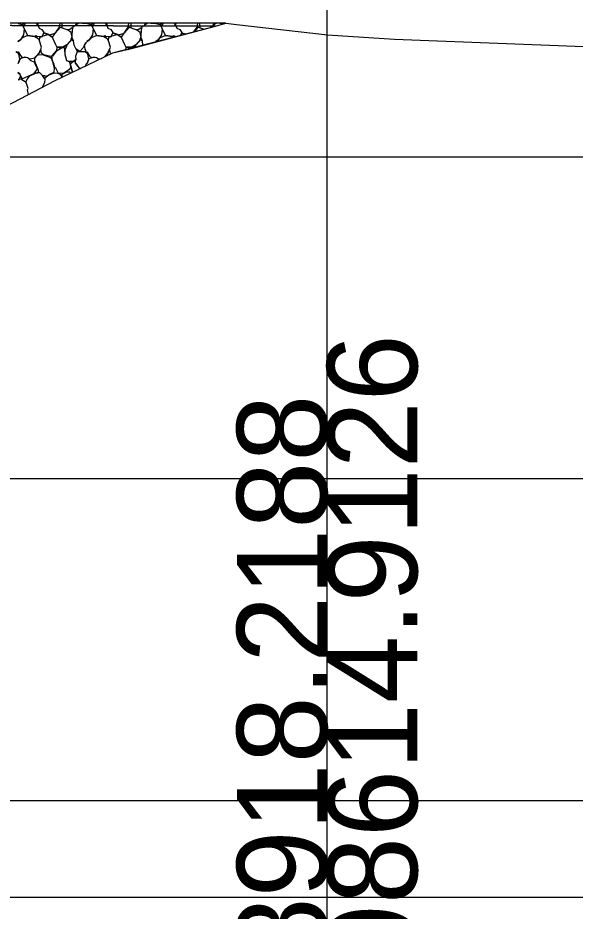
# Model space of a CAD drawing. Extents: x -26 to 2998798, y -429 to 819149.
# Drawn here: x 290.4 to 307.7, y 2499.57 to 2527.31 of the extents above; entities that cross this region are included whole.
import ezdxf

# ---------------------------------------------------------------- set-up
doc = ezdxf.new("R2010")
doc.units = 0
for name, color, linetype in [('DESIGN - EARTHWORK - Shapes', 7, 'Continuous'), ('DESIGN - PROFILE - Patterning', 7, 'Continuous'), ('DESIGN - SCRATCH - User 3', 7, 'Continuous'), ('DESIGN - SHEET - Light Grid', 7, 'Continuous'), ('DESIGN - SHEET - Linework', 7, 'Continuous'), ('DESIGN - TYPICAL - Finished Grade and Subgrade', 7, 'Continuous'), ('SURVEY - GROUND - Top of Ground', 7, 'Continuous')]:
    doc.layers.add(name, color=color, linetype=linetype)

msp = doc.modelspace()

# ---------------------------------------------------------------- linework, layer by layer
at = {"layer": 'DESIGN - EARTHWORK - Shapes'}
msp.add_lwpolyline([(281.017, 2547.801), (225.777, 2510.974), (230.186, 2511.075), (242.134, 2511.654), (249.866, 2511.679), (265.88, 2511.997), (267.637, 2514.832), (268.915, 2514.926), (272.672, 2515.326), (273.716, 2515.78), (276.491, 2517.642), (280.232, 2519.336), (286.77, 2522.859), (291.559, 2525.363), (293.354, 2526.226), (293.926, 2526.362), (296.534, 2527.058), (296.854, 2527.144), (297.186, 2527.106), (300.012, 2526.786), (302.093, 2526.657), (307.973, 2526.42)], dxfattribs=at)
at = {"layer": 'DESIGN - PROFILE - Patterning'}
for p, q in [((296.854, 2527.144), (268.06, 2527.144)), ((291.764, 2527.144), (291.769, 2527.001)), ((293.904, 2527.144), (293.909, 2527.001)), ((296.044, 2527.144), (296.049, 2527.001))]:
    msp.add_line(p, q, dxfattribs=at)
for points in [[(225.777, 2510.974), (230.186, 2511.075), (242.134, 2511.654), (249.866, 2511.679), (265.88, 2511.997), (267.637, 2514.832), (268.117, 2514.851), (268.915, 2514.926), (272.672, 2515.326), (273.716, 2515.78), (276.491, 2517.642), (280.232, 2519.336), (286.77, 2522.859), (291.559, 2525.363), (293.354, 2526.226), (293.926, 2526.362), (296.534, 2527.058), (296.854, 2527.144)], [(291.025, 2527.144), (291.019, 2527.091), (291.059, 2526.996), (291.149, 2526.951), (291.209, 2526.856), (291.159, 2526.741), (291.229, 2526.771), (291.334, 2526.796), (291.339, 2526.806), (291.194, 2526.851), (291.384, 2526.791), (291.564, 2526.841), (291.719, 2527.016), (291.679, 2527.026), (291.469, 2526.716), (291.349, 2526.801), (291.469, 2526.711), (291.569, 2526.486), (291.609, 2526.401), (291.599, 2526.291), (291.754, 2526.381), (291.809, 2526.406), (291.924, 2526.476), (291.794, 2526.401), (291.609, 2526.406), (291.759, 2526.381), (291.839, 2526.396), (291.849, 2526.321), (291.859, 2526.181), (291.909, 2525.986), (291.999, 2525.961), (292.024, 2525.886), (292.034, 2525.761), (291.979, 2525.696), (291.894, 2525.636), (291.824, 2525.596), (291.664, 2525.586), (291.584, 2525.746), (291.544, 2525.771), (291.509, 2525.921), (291.469, 2525.986), (291.469, 2526.071), (291.459, 2526.126), (291.604, 2526.286), (291.474, 2526.121), (291.429, 2526.116), (291.244, 2526.151), (291.199, 2526.161), (291.134, 2526.216), (291.109, 2526.331), (291.134, 2526.401), (291.074, 2526.596), (291.084, 2526.711), (291.164, 2526.731), (291.009, 2526.726), (290.959, 2526.751), (290.924, 2526.736), (290.709, 2526.766), (290.599, 2526.981), (290.569, 2527.041), (290.599, 2526.976), (290.579, 2526.786), (290.479, 2526.631), (290.404, 2526.576), (290.484, 2526.636), (290.554, 2526.701), (290.694, 2526.761), (290.929, 2526.731), (291.029, 2526.676), (291.069, 2526.596)], [(290.409, 2527.136), (290.539, 2527.111), (290.574, 2527.036), (290.641, 2527.144)], [(290.595, 2527.144), (290.534, 2527.111), (290.594, 2527.144)], [(290.974, 2527.144), (291.009, 2527.091), (291.024, 2527.144)], [(292.351, 2525.744), (292.319, 2525.746), (292.189, 2525.906), (292.194, 2526.006), (292.149, 2525.981), (292.209, 2526.006), (292.204, 2526.131), (292.254, 2526.266), (292.344, 2526.271), (292.479, 2526.266), (292.544, 2526.226), (292.499, 2526.261), (292.524, 2526.286), (292.489, 2526.346), (292.474, 2526.461), (292.504, 2526.536), (292.529, 2526.561), (292.509, 2526.541), (292.459, 2526.451), (292.419, 2526.376), (292.324, 2526.271), (292.209, 2526.341), (292.254, 2526.271), (292.209, 2526.346), (292.144, 2526.461), (292.129, 2526.601), (292.059, 2526.621), (292.059, 2526.676), (292.099, 2526.661), (292.124, 2526.601), (292.094, 2526.661), (292.059, 2526.861), (291.939, 2526.941), (292.019, 2526.961), (292.069, 2527.001), (292.094, 2526.996), (292.059, 2526.996), (292.019, 2526.951), (291.929, 2526.941), (291.724, 2527.011), (291.689, 2527.026), (291.709, 2527.141), (291.71, 2527.144)], [(292.229, 2527.144), (292.189, 2527.081), (292.094, 2527.011), (292.079, 2526.801), (292.064, 2526.641), (291.929, 2526.491), (291.854, 2526.311), (291.859, 2526.176), (291.914, 2525.991), (291.989, 2525.956), (292.029, 2525.881), (292.099, 2525.623)], [(292.299, 2527.144), (292.189, 2527.091), (292.222, 2527.144)], [(292.398, 2527.144), (292.399, 2527.141), (292.375, 2527.144)], [(292.534, 2527.136), (292.404, 2527.141), (292.403, 2527.144)], [(293.296, 2526.198), (293.274, 2526.216), (293.249, 2526.331), (293.274, 2526.401), (293.214, 2526.596), (293.224, 2526.711), (293.304, 2526.731), (293.149, 2526.726), (293.099, 2526.751), (293.064, 2526.736), (292.849, 2526.766), (292.739, 2526.981), (292.709, 2527.041), (292.739, 2526.976), (292.719, 2526.786), (292.619, 2526.631), (292.544, 2526.576), (292.624, 2526.636), (292.694, 2526.701), (292.834, 2526.761), (293.069, 2526.731), (293.169, 2526.676), (293.209, 2526.596)], [(292.549, 2527.136), (292.679, 2527.111), (292.714, 2527.036), (292.781, 2527.144)], [(292.735, 2527.144), (292.674, 2527.111), (292.734, 2527.144)], [(293.114, 2527.144), (293.149, 2527.091), (293.164, 2527.144)], [(293.165, 2527.144), (293.159, 2527.091), (293.199, 2526.996), (293.289, 2526.951), (293.349, 2526.856), (293.299, 2526.741), (293.369, 2526.771), (293.474, 2526.796), (293.479, 2526.806), (293.334, 2526.851), (293.524, 2526.791), (293.704, 2526.841), (293.859, 2527.016), (293.819, 2527.026), (293.609, 2526.716), (293.489, 2526.801), (293.609, 2526.711), (293.709, 2526.486), (293.749, 2526.401), (293.741, 2526.318)], [(294.286, 2526.458), (294.284, 2526.461), (294.269, 2526.601), (294.199, 2526.621), (294.199, 2526.676), (294.239, 2526.661), (294.264, 2526.601), (294.234, 2526.661), (294.199, 2526.861), (294.079, 2526.941), (294.159, 2526.961), (294.209, 2527.001), (294.234, 2526.996), (294.199, 2526.996), (294.159, 2526.951), (294.069, 2526.941), (293.864, 2527.011), (293.829, 2527.026), (293.849, 2527.141), (293.85, 2527.144)], [(294.369, 2527.144), (294.329, 2527.081), (294.234, 2527.011), (294.219, 2526.801), (294.204, 2526.641), (294.069, 2526.491), (294.026, 2526.388)], [(294.439, 2527.144), (294.329, 2527.091), (294.362, 2527.144)], [(294.538, 2527.144), (294.539, 2527.141), (294.515, 2527.144)], [(294.674, 2527.136), (294.544, 2527.141), (294.543, 2527.144)], [(295.291, 2526.726), (295.289, 2526.726), (295.239, 2526.751), (295.204, 2526.736), (294.989, 2526.766), (294.879, 2526.981), (294.849, 2527.041), (294.879, 2526.976), (294.859, 2526.786), (294.759, 2526.631), (294.684, 2526.576), (294.764, 2526.636), (294.834, 2526.701), (294.974, 2526.761), (295.209, 2526.731), (295.242, 2526.713)], [(294.689, 2527.136), (294.819, 2527.111), (294.854, 2527.036), (294.921, 2527.144)], [(294.875, 2527.144), (294.814, 2527.111), (294.874, 2527.144)], [(295.254, 2527.144), (295.289, 2527.091), (295.304, 2527.144)], [(295.305, 2527.144), (295.299, 2527.091), (295.339, 2526.996), (295.429, 2526.951), (295.489, 2526.856), (295.451, 2526.769)], [(296.159, 2526.958), (296.004, 2527.011), (295.969, 2527.026), (295.989, 2527.141), (295.99, 2527.144)], [(296.509, 2527.144), (296.469, 2527.081), (296.383, 2527.018)], [(296.579, 2527.144), (296.469, 2527.091), (296.502, 2527.144)], [(296.678, 2527.144), (296.679, 2527.141), (296.655, 2527.144)], [(296.814, 2527.136), (296.684, 2527.141), (296.683, 2527.144)], [(295.605, 2526.81), (295.474, 2526.851), (295.604, 2526.81)], [(295.882, 2526.884), (295.999, 2527.016), (295.959, 2527.026), (295.858, 2526.878)], [(293.814, 2526.335), (293.894, 2526.381), (293.949, 2526.406), (294.064, 2526.476), (293.934, 2526.401), (293.749, 2526.406), (293.899, 2526.381), (293.979, 2526.396), (293.981, 2526.376)], [(294.667, 2526.56), (294.669, 2526.561), (294.667, 2526.56)], [(290.339, 2526.266), (290.404, 2526.226), (290.359, 2526.261)], [(290.736, 2524.933), (290.704, 2525.076), (290.719, 2525.116), (290.659, 2525.301), (290.489, 2525.406), (290.409, 2525.391), (290.454, 2525.401), (290.449, 2525.426), (290.479, 2525.486), (290.494, 2525.486), (290.469, 2525.566), (290.404, 2525.621), (290.459, 2525.566), (290.504, 2525.486), (290.509, 2525.456), (290.554, 2525.431), (290.739, 2525.511), (290.914, 2525.576), (290.744, 2525.496), (290.704, 2525.426), (290.649, 2525.326), (290.704, 2525.421), (290.739, 2525.496), (290.739, 2525.516), (290.909, 2525.586), (291.009, 2525.731), (290.939, 2525.876), (290.924, 2525.926), (290.794, 2525.991), (290.754, 2526.031), (290.709, 2526.076), (290.604, 2526.091), (290.554, 2526.076), (290.469, 2526.036), (290.409, 2525.891), (290.459, 2526.031), (290.429, 2526.191), (290.404, 2526.221), (290.434, 2526.221), (290.414, 2526.261), (290.499, 2526.111), (290.559, 2526.081), (290.609, 2526.091), (290.704, 2526.081), (290.764, 2526.036), (290.934, 2526.071), (291.059, 2526.221), (291.099, 2526.321), (291.059, 2526.221), (290.979, 2526.136), (290.919, 2526.071), (290.914, 2525.976), (290.934, 2525.916), (291.024, 2525.721), (291.044, 2525.616), (290.914, 2525.581), (291.069, 2525.616), (291.164, 2525.526), (291.234, 2525.406), (291.229, 2525.306), (291.169, 2525.171), (291.172, 2525.161)], [(292.912, 2526.013), (292.894, 2526.031), (292.849, 2526.076), (292.744, 2526.091), (292.694, 2526.076), (292.609, 2526.036), (292.549, 2525.891), (292.599, 2526.031), (292.569, 2526.191), (292.544, 2526.221), (292.574, 2526.221), (292.554, 2526.261), (292.639, 2526.111), (292.699, 2526.081), (292.749, 2526.091), (292.844, 2526.081), (292.904, 2526.036), (293.001, 2526.056)], [(293.101, 2526.104), (293.199, 2526.221), (293.239, 2526.321), (293.199, 2526.221), (293.119, 2526.136), (293.08, 2526.094)], [(290.994, 2526.151), (291.084, 2526.171), (291.184, 2526.161), (291.414, 2526.086), (291.469, 2526.001), (291.529, 2525.766), (291.514, 2525.616), (291.399, 2525.561), (291.364, 2525.531), (291.229, 2525.431), (291.164, 2525.526), (291.229, 2525.526), (291.279, 2525.506), (291.354, 2525.531), (291.529, 2525.611), (291.634, 2525.596), (291.689, 2525.576), (291.778, 2525.468)], [(292.097, 2525.622), (292.024, 2525.881), (292.084, 2525.941), (292.149, 2525.971), (291.984, 2525.961), (292.159, 2525.971), (292.199, 2525.901), (292.309, 2525.756), (292.349, 2525.743)], [(293.134, 2526.151), (293.224, 2526.171), (293.238, 2526.17)], [(292.503, 2525.817), (292.534, 2525.891), (292.495, 2525.813)], [(291.781, 2525.47), (291.779, 2525.476), (291.779, 2525.566), (291.899, 2525.636), (292.004, 2525.636), (292.043, 2525.596)]]:
    msp.add_lwpolyline(points, dxfattribs=at)
at = {"layer": 'DESIGN - SCRATCH - User 3'}
msp.add_lwpolyline([(299.208, 2547.909), (289, 2547.848), (281.017, 2547.801), (225.777, 2510.974), (230.186, 2511.075), (242.134, 2511.654), (249.866, 2511.679), (265.88, 2511.997), (267.637, 2514.832), (268.915, 2514.926), (272.672, 2515.326), (273.716, 2515.78), (276.491, 2517.642), (280.232, 2519.336), (286.77, 2522.859), (291.559, 2525.363), (293.354, 2526.226), (296.534, 2527.058), (268.06, 2527.144)], close=True, dxfattribs=at)
at = {"layer": 'DESIGN - SHEET - Light Grid'}
for p, q in [((300, 2500), (300, 2695.149)), ((0, 2500), (300, 2500)), ((300, 2500), (600, 2500))]:
    msp.add_line(p, q, dxfattribs=at)
at = {"layer": 'DESIGN - SHEET - Linework'}
for p, q in [((300, 2443), (300, 2653)), ((150, 2523), (450, 2523)), ((150, 2513), (450, 2513)), ((150, 2503), (450, 2503))]:
    msp.add_line(p, q, dxfattribs=at)
at = {"layer": 'DESIGN - TYPICAL - Finished Grade and Subgrade'}
msp.add_line((296.854, 2527.144), (296.854, 2527.144), dxfattribs=at)
msp.add_lwpolyline([(299.208, 2547.909), (268.06, 2527.144), (296.534, 2527.058)], dxfattribs=at)
at = {"layer": 'SURVEY - GROUND - Top of Ground'}
msp.add_lwpolyline([(206.456, 2510.529), (230.186, 2511.075), (242.134, 2511.654), (249.866, 2511.679), (265.88, 2511.997), (267.637, 2514.832), (268.117, 2514.851), (268.915, 2514.926), (272.672, 2515.326), (273.716, 2515.78), (276.491, 2517.642), (280.232, 2519.336), (286.77, 2522.859), (291.559, 2525.363), (293.354, 2526.226), (293.926, 2526.362), (296.534, 2527.058), (296.854, 2527.144), (297.186, 2527.106), (300.012, 2526.786), (302.093, 2526.657), (307.973, 2526.42)], dxfattribs=at)

# ---------------------------------------------------------------- texts
at = {"layer": 'DESIGN - SHEET - Light Grid'}
for s, p in [('E 2998614.9126', (302.8, 2490)), ('N 818918.2188', (300, 2490))]:
    msp.add_text(s, height=2.8, rotation=90, dxfattribs=at).set_placement(p)

doc.saveas('drawing.dxf')
